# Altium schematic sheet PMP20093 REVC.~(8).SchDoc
size 431 x 279 mm; Date: Not shown in title block; ApprovedBy: Not shown in title block; CheckedBy: Not shown in title block; Author: Not shown in title block; CompanyName: Not shown in title block; Engineer: Not shown in title block; Organization: Not shown in title block; Address1: Not shown in title block; Address2: Not shown in title block; Address3: Not shown in title block; Address4: Not shown in title block; DocumentNumber: 1; Revision: Use project parameter SCH_Rev; SheetNumber: 1; SheetTotal: 1; PageSetup: Record=PageOptions¦CenterHorizontal=True¦CenterVertical=True¦PrintScale=1.00¦XCorrection=1.00¦YCorrection=1.00¦PrintKind=0¦BorderSize=5000000¦LeftOffset=0¦BottomOffset=0¦Orientation=2¦PaperLength=1000¦PaperWidth=1000¦Scale=100¦PaperSource=15¦PrintQuality=600¦MediaType=1¦DitherType=10¦PaperKind=Letter¦PrintScaleMode=1
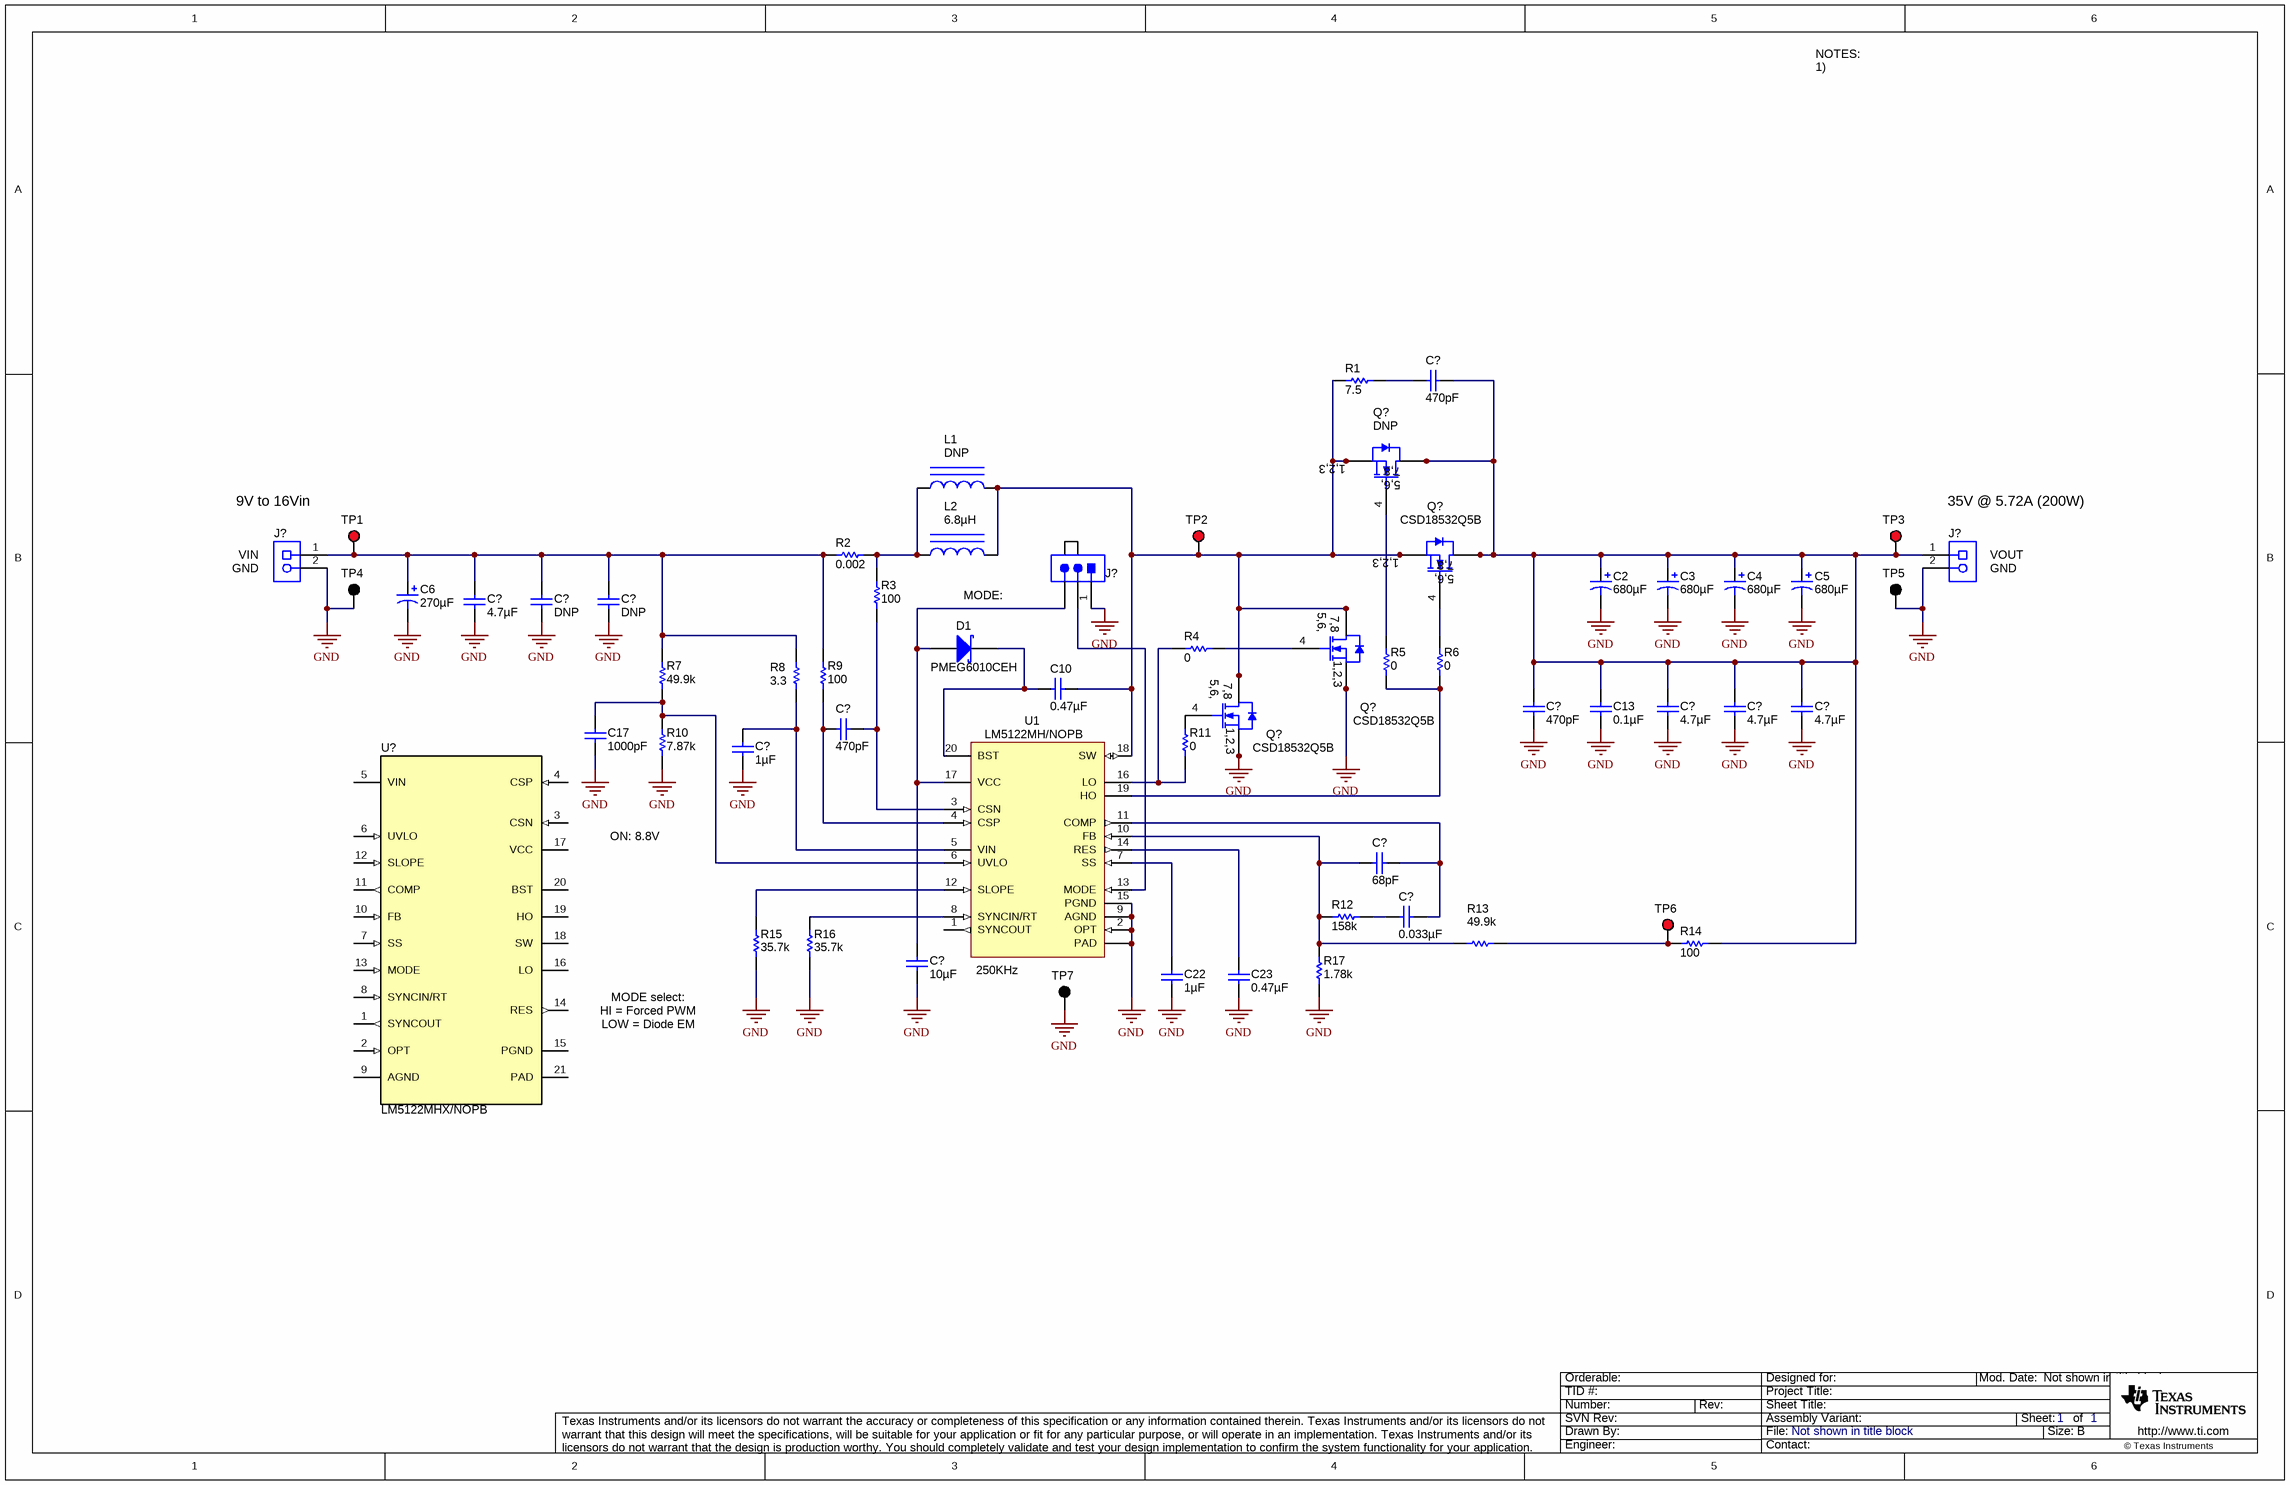
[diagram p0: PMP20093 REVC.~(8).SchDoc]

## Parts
(Parts that share a designator on the sheet are numbered #1, #2 ... from top to bottom, then left to right.)
C2  ValueDisplayed: 680µF  [ZL_1250x2500]  (hidden comment: 50ZL680MEFC12.5X25)
C3  ValueDisplayed: 680µF  [ZL_1250x2500]  (hidden comment: 50ZL680MEFC12.5X25)
C4  ValueDisplayed: 680µF  [ZL_1250x2500]  (hidden comment: 50ZL680MEFC12.5X25)
C5  ValueDisplayed: 680µF  [ZL_1250x2500]  (hidden comment: 50ZL680MEFC12.5X25)
C6  ValueDisplayed: 270µF  [SM_RADIAL_10BMM]  (hidden comment: EEHZA1V271P)
C10  ValueDisplayed: 0.47µF  [0603]  (hidden comment: GRM188R71E474KA12D)
C13  ValueDisplayed: 0.1µF  [0603]  (hidden comment: C1608X7R1H104K080AA)
C17  ValueDisplayed: 1000pF  [0603]  (hidden comment: GRM188R71H102KA01D)
C22  ValueDisplayed: 1µF  [0603]  (hidden comment: C1608X7R1E105K080AB)
C23  ValueDisplayed: 0.47µF  [0603]  (hidden comment: GRM188R71E474KA12D)
C?#1  ValueDisplayed: 470pF  [0603]  (hidden comment: C1608C0G2A471J)
C?#2  ValueDisplayed: 4.7µF  [1210_270]  (hidden comment: GRM32ER71H475KA88L)
C?#3  ValueDisplayed: DNP  [1210_270]
C?#4  ValueDisplayed: DNP  [1210_270]
C?#5  ValueDisplayed: 470pF  [0603]  (hidden comment: C1608C0G2A471J)
C?#6  ValueDisplayed: 4.7µF  [1210_270]  (hidden comment: GRM32ER71H475KA88L)
C?#7  ValueDisplayed: 4.7µF  [1210_270]  (hidden comment: GRM32ER71H475KA88L)
C?#8  ValueDisplayed: 4.7µF  [1210_270]  (hidden comment: GRM32ER71H475KA88L)
C?#9  ValueDisplayed: 470pF  [0603]  (hidden comment: C1608C0G2A471J)
C?#10  ValueDisplayed: 1µF  [0805_HV]  (hidden comment: C2012X7R1H105K125AB)
C?#11  ValueDisplayed: 68pF  [0603]  (hidden comment: GRM1885C1H680JA01D)
C?#12  ValueDisplayed: 0.033µF  [0603]  (hidden comment: GRM188R71H333KA61D)
C?#13  ValueDisplayed: 10µF  [0805_HV]  (hidden comment: GRM21BZ71E106KE15L)
D1  PMEG6010CEH  [SOD-123F]
J?#1  ED120/2DS  [On-Shore_ED120_2DS]  (value not drawn)
J?#2  ED120/2DS  [On-Shore_ED120_2DS]  (value not drawn)
J?#3  PEC03SAAN  [CONN_PEC03SAAN]  (value not drawn)
L1  ValueDisplayed: DNP  [XAL1010]
L2  ValueDisplayed: 6.8µH  [IHLP8787MZ]  (hidden comment: IHLP8787MZER6R8M5A)
Q?#1  value DNP  [DNK0008A]
Q?#2  CSD18532Q5B  [DNK0008A]
Q?#3  CSD18532Q5B  [DNK0008A]
Q?#4  CSD18532Q5B  [DNK0008A]
R1  value 7.5  [2010M]  (hidden comment: CRM2010-JW-7R5ELF)
R2  value 0.002  [2512]  (hidden comment: CSNL2512FT2L00)
R3  ValueDisplayed: 100  [0603]  (hidden comment: CRCW0603100RFKEA)
R4  ValueDisplayed: 0  [0603]  (hidden comment: CRCW06030000Z0EA)
R5  ValueDisplayed: 0  [0603]  (hidden comment: CRCW06030000Z0EA)
R6  ValueDisplayed: 0  [0603]  (hidden comment: CRCW06030000Z0EA)
R7  value 49.9k  [0603]  (hidden comment: CRCW060349K9FKEA)
R8  value 3.3  [0603_HV]  (hidden comment: CRCW06033R30JNEA)
R9  ValueDisplayed: 100  [0603]  (hidden comment: CRCW0603100RFKEA)
R10  ValueDisplayed: 7.87k  [0603]  (hidden comment: CRCW06037K87FKEA)
R11  ValueDisplayed: 0  [0603]  (hidden comment: CRCW06030000Z0EA)
R12  ValueDisplayed: 158k  [0603]  (hidden comment: CRCW0603158KFKEA)
R13  value 49.9k  [0603]  (hidden comment: CRCW060349K9FKEA)
R14  value 100  [0603]  (hidden comment: CRCW0603100RFKEA)
R15  ValueDisplayed: 35.7k  [0603]  (hidden comment: CRCW060335K7FKEA)
R16  ValueDisplayed: 35.7k  [0603]  (hidden comment: CRCW060335K7FKEA)
R17  ValueDisplayed: 1.78k  [0603]  (hidden comment: CRCW06031K78FKEA)
TP1  5010  [Keystone5010]  (value not drawn)
TP2  5010  [Keystone5010]  (value not drawn)
TP3  5010  [Keystone5010]  (value not drawn)
TP4  5011  [Keystone5011]  (value not drawn)
TP5  5011  [Keystone5011]  (value not drawn)
TP6  5010  [Keystone5010]  (value not drawn)
TP7  5011  [Keystone5011]  (value not drawn)
U1  LM5122MH/NOPB  [PWP0020A_N]
U?  LM5122MHX/NOPB  [PWP0020A_N]

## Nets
GND: C2.2(-) C3.2(-) C4.2(-) C5.2(-) C6.2(-) C13.1 C17.2 C22.2 C23.1 C?#2.2 C?#3.2 C?#4.2 C?#5.2 C?#6.2 C?#7.2 C?#8.2 C?#10.1 C?#13.2 J?#1.2 J?#2.2 J?#3.1 Q?#3.1(S) Q?#3.2(S) Q?#3.3(S) Q?#4.1(S) Q?#4.2(S) Q?#4.3(S) R10.1 R15.1 R16.1 R17.1 TP4.1 TP5.1 TP7.1 U1.2(OPT) U1.9(AGND) U1.15(PGND) U1.21(PAD)
NetC2_1: C2.1(+) C3.1(+) C4.1(+) C5.1(+) C13.2 C?#1.1 C?#5.1 C?#6.1 C?#7.1 C?#8.1 J?#2.1 Q?#1.5(D) Q?#1.6(D) Q?#1.7(D) Q?#1.8(D) Q?#1.9(D) Q?#2.5(D) Q?#2.6(D) Q?#2.7(D) Q?#2.8(D) Q?#2.9(D) R14.2 TP3.1
NetC6_1: C6.1(+) C?#2.1 C?#3.1 C?#4.1 J?#1.1 R2.1 R7.2 R8.1 R9.2 TP1.1
NetC10_1: C10.1 D1.1(K) U1.20(BST)
NetC10_2: C10.2 L1.2 L2.2 Q?#1.1(S) Q?#1.2(S) Q?#1.3(S) Q?#2.1(S) Q?#2.2(S) Q?#2.3(S) Q?#3.5(D) Q?#3.6(D) Q?#3.7(D) Q?#3.8(D) Q?#3.9(D) Q?#4.5(D) Q?#4.6(D) Q?#4.7(D) Q?#4.8(D) Q?#4.9(D) R1.1 TP2.1 U1.18(SW)
NetC17_1: C17.1 R7.1 R10.2 U1.6(UVLO)
NetC22_1: C22.1 U1.7(SS)
NetC23_2: C23.2 U1.14(RES)
NetC?#1_2: C?#1.2 R1.2
NetC?#9_1: C?#9.1 R3.1 U1.3(CSN)
NetC?#9_2: C?#9.2 R9.1 U1.4(CSP)
NetC?#10_2: C?#10.2 R8.2 U1.5(VIN)
NetC?#11_1: C?#11.1 C?#12.1 U1.11(COMP)
NetC?#11_2: C?#11.2 R12.1 R13.1 R17.2 U1.10(FB)
NetC?#12_2: C?#12.2 R12.2
NetC?#13_1: C?#13.1 D1.2(A) J?#3.3 U1.17(VCC)
NetJ?#3_2: J?#3.2 U1.13(MODE)
NetL1_1: L1.1 L2.1 R2.2 R3.2
NetQ?#1_4: Q?#1.4(G) R5.2
NetQ?#2_4: Q?#2.4(G) R6.2
NetQ?#3_4: Q?#3.4(G) R4.1
NetQ?#4_4: Q?#4.4(G) R11.2
NetR4_2: R4.2 R11.1 U1.16(LO)
NetR5_1: R5.1 R6.1 U1.19(HO)
NetR13_2: R13.2 R14.1 TP6.1
NetR15_2: R15.2 U1.12(SLOPE)
NetR16_2: R16.2 U1.8(SYNCIN/RT)

Not connected (* = marked no-connect by the designer): U1 1(SYNCOUT); U? 1(SYNCOUT) 2(OPT) 3(CSN) 4(CSP) 5(VIN) 6(UVLO) 7(SS) 8(SYNCIN/RT) 9(AGND) 10(FB) 11(COMP) 12(SLOPE) 13(MODE) 14(RES) 15(PGND) 16(LO) 17(VCC) 18(SW) 19(HO) 20(BST) 21(PAD)

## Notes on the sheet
- NOTES:
  1)
- 9V to 16Vin
- 35V @ 5.72A (200W)
- (near J?#1) VIN
- (near J?#1) GND
- (near J?#2) VOUT
- (near J?#2) GND
- MODE:
- ON: 8.8V
- (near U1) 250KHz
- MODE select:
- HI = Forced PWM
- LOW = Diode EM

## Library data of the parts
C2-C5 = 50ZL560MEFC12.5X25: CAP, AL, 680 µF, 50 V, +/- 20%, 2.86A, 0.021 ohm, TH; Manufacturer: Rubycon; Polarized: Y; CompType: Capacitor; Value: 680uF; U/M: EA; Cap_F: 0.00056; Tolerance_%: 20; VDC_V: 50; Value2: 50V; ESR_ohm: 0.023; IRMS_A: 2.41; TaMin_C: -40; TaMax_C: 105; Cap_Case: 12.5x25mm; AEC Category: Q200; AEC Qualified: N
C6 = EEHZA1V271P: CAP, Polymer Hybrid, 270 µF, 35 V, +/- 20%, 20 ohm, 10x10 SMD; Manufacturer: Panasonic; Polarized: Y; CompType: Capacitor; Value: 270uF; U/M: EA; Cap_F: 0.00027; Tolerance_%: 20; Value1: 20 ohm; VDC_V: 35; Value2: 35V; IRMS_A: 2.5; TaMin_C: -55; TaMax_C: 105; AEC Category: Q200
C10 C23 = GRM188R71E474KA12D: CAP, CERM, 0.47uF, 25V, +/-10%, X7R, 0603; Manufacturer: MuRata; Polarized: N; CompType: Capacitor; U/M: EA; Cap_F: 0.00000047; Tolerance_%: 10; Value1: Unknown; VDC_V: 25; TaMin_C: -55; TaMax_C: 125
C13 = C1608X7R1H104K080AA: CAP, CERM, 0.1 µF, 50 V, +/- 10%, X7R, 0603; Manufacturer: TDK; Polarized: N; CompType: Capacitor; Value: 0.1uF; U/M: EA; Cap_F: 0.0000001; Tolerance_%: 10; ESR_ohm: 0.0296; Value1: 0.0296 ohm; VDC_V: 50; Value2: 50V; IRMS_A: 0.97199; TaMin_C: -55; TaMax_C: 125; AEC Category: Q200; SizeArea_mm2: 1.28; SizeAreaWB_mm2: 4.68; SizeX_mm: 1.6; SizeY_mm: 0.8; SizeZ_mm: 1
C17 = GRM188R71H102KA01D: CAP, CERM, 1000pF, 50V, +/-10%, X7R, 0603; Manufacturer: MuRata; Polarized: N; CompType: Capacitor; U/M: EA; Cap_F: 0.000000001; Tolerance_%: 10; Value1: Unknown; VDC_V: 50; TaMin_C: -55; TaMax_C: 125
C22 = C1608X7R1E105K080AB: CAP, CERM, 1 µF, 25 V, +/- 10%, X7R, 0603; Manufacturer: TDK; Polarized: N; CompType: Capacitor; Value: 1uF; U/M: EA; Cap_F: 0.000001; Tolerance_%: 10; Value1: Unknown; VDC_V: 25; Value2: 25V; TaMin_C: -55; TaMax_C: 125; AEC Category: Q200
C?#1 C?#5 C?#9 = C1608C0G2A471J: CAP, CERM, 470 pF, 100 V, +/- 5%, C0G/NP0, 0603; Manufacturer: TDK; Polarized: N; CompType: Capacitor; Value: 470pF; U/M: EA; Cap_F: 0.00000000047; Tolerance_%: 5; ESR_ohm: 0.0714; Value1: 0.0714 ohm; VDC_V: 100; Value2: 100V; TaMin_C: -55; TaMax_C: 125; SizeArea_mm2: 1.28; SizeAreaWB_mm2: 4.68; SizeX_mm: 1.6; SizeY_mm: 0.8; SizeZ_mm: 1; AEC Category: Q200
C?#2 C?#6-C?#8 = GRM32ER71H475KA88L: CAP, CERM, 4.7 µF, 50 V, +/- 10%, X7R, 1210; Manufacturer: MuRata; Polarized: N; CompType: Capacitor; Value: 4.7uF; U/M: EA; Cap_F: 0.0000047; Tolerance_%: 10; ESR_ohm: 0.002; Value1: 0.002 ohm; VDC_V: 50; Value2: 50V; TaMin_C: -55; TaMax_C: 125; Cap_Case: 1210; SizeArea_mm2: 8; SizeAreaWB_mm2: 14.7; SizeX_mm: 3.2; SizeY_mm: 2.5; SizeZ_mm: 2.7; AEC Category: Q200
C?#3 C?#4 = GRM32ER71H475KA88L: CAP, CERM, 1210; Polarized: N; CompType: Capacitor; U/M: EA; Tolerance_%: 10; ESR_ohm: 0.002; TaMin_C: -55; TaMax_C: 125; Cap_Case: 1210; SizeArea_mm2: 8; SizeAreaWB_mm2: 14.7; AEC Category: Q200
C?#10 = C2012X7R1H105K125AB: CAP, CERM, 1 µF, 50 V, +/- 10%, X7R, 0805; Manufacturer: TDK; Polarized: N; CompType: Capacitor; Value: 1uF; U/M: EA; Cap_F: 0.000001; Tolerance_%: 10; ESR_ohm: 0.008782; Value1: 0.008782 ohm; VDC_V: 50; Value2: 50V; IRMS_A: 2.20488; TaMin_C: -55; TaMax_C: 125; Cap_Case: 0805; SizeArea_mm2: 2.5; SizeAreaWB_mm2: 6.75; SizeX_mm: 2; SizeY_mm: 1.25; SizeZ_mm: 1.45; AEC Category: Q200
C?#11 = GRM1885C1H680JA01D: CAP, CERM, 68 pF, 50 V, +/- 5%, C0G/NP0, 0603; Manufacturer: MuRata; Polarized: N; CompType: Capacitor; Value: 68pF; U/M: EA; Cap_F: 0.000000000068; Tolerance_%: 5; Value1: Unknown; VDC_V: 50; Value2: 50V; TaMin_C: -55; TaMax_C: 125; SizeArea_mm2: 1.28; SizeAreaWB_mm2: 4.68; SizeX_mm: 1.6; SizeY_mm: 0.8; SizeZ_mm: 1; AEC Category: Q200
C?#12 = GRM188R71H333KA61D: CAP, CERM, 0.033 µF, 50 V, +/- 10%, X7R, 0603; Manufacturer: MuRata; Polarized: N; CompType: Capacitor; Value: 0.033uF; U/M: EA; Cap_F: 0.000000033; Tolerance_%: 10; Value1: Unknown; VDC_V: 50; Value2: 50V; TaMin_C: -55; TaMax_C: 125; SizeArea_mm2: 1.28; SizeAreaWB_mm2: 4.68; SizeX_mm: 1.6; SizeY_mm: 0.8; SizeZ_mm: 1; AEC Category: Q200
C?#13 = GRM21BZ71E106KE15L: CAP, CERM, 10 µF, 25 V, +/- 10%, X7R, 0805; Manufacturer: MuRata; Polarized: N; CompType: Capacitor; Value: 10uF; U/M: EA; Cap_F: 0.00001; Tolerance_%: 10; Value1: Unknown; VDC_V: 25; Value2: 25V; TaMin_C: -55; TaMax_C: 125; Cap_Case: 0805; SizeArea_mm2: 2.5; SizeAreaWB_mm2: 6.75; SizeX_mm: 2; SizeY_mm: 1.25; SizeZ_mm: 1.45; AEC Category: Q200
D1 = PMEG6010CEH,115: Diode, Schottky, 60V, 1A, SOD-123F; Manufacturer: NXP Semiconductor; U/M: EA; Vf_V: 0.57; Value2: 0.57V; Io_A: 1; Vr_V: 60; TJmax_C: 150
J?#1 J?#2 = ED120/2DS: Terminal Block, 5.08 mm, 2x1, Brass, TH; Manufacturer: On-Shore Technology; SymbolCreator: a0412235; Pitch_mm: 5.08; Gender: Female; Shrouded: N; Row_Count: 1; Current_A: 15; Voltage_V: 300; Cert_CULUS: Y
J?#3 = PEC03SAAN: Header, 100mil, 3x1, Tin, TH; Manufacturer: Sullins Connector Solutions; SymbolCreator: a0799628; Pitch_mm: 2.54; Gender: Male; Shrouded: N; Row_Count: 1; Current_A: 3; Voltage_V: 1800; Cert_UL: Y
L1 = XAL1010-222MEB: Inductor, SMD, alternate footprint; U/M: EA
L2 = IHLP8787MZER100M5A: Inductor, Shielded, 6.8 µH, 36A, 0.00284 ohm, AEC-Q200 Grade 0, SMD; Manufacturer: Vishay-Dale; Value: 6.8uH; AEC Category: Q200; AEC Qualified: Y; AEC Grade: 0
Q?#1 = CSD18532Q5B: MOSFET, N-CH, DNP; Alternate Manufacturer: None; U/M: EA; ChType: N; IdsMax_A: 172; SizeAreaWB_mm2: 56; SizeArea_mm2: 30; AEC Category: Q101
Q?#2-Q?#4 = CSD18532Q5B: MOSFET, N-CH, 60 V, 172 A, DNK0008A (VSON-CLIP-8); Manufacturer: Texas Instruments; Alternate Manufacturer: None; U/M: EA; ChType: N; Value: 60V; VdsMax_V: 60; Value1: 3.3 ohm; Rdson45_ohm: 3.3; Value2: 27 nC; QgTyp_nC: 27; Vgs_V: 1.6; IdsMax_A: 172; SizeAreaWB_mm2: 56; SizeArea_mm2: 30; SizeX_mm: 6; SizeY_mm: 5; SizeZ_mm: 1; AEC Category: Q101
R1 = CRM2010-JW-7R5ELF: RES, 7.5 ohm, 5%, 1W, 2010; Manufacturer: Bourns; CompType: Resistor; Value_Code: 7R50; Tolerance_%: 5; Power_W: 1; VDC_V: 3; TempCo: 100 ppm/C; EIA_Code: E24; U/M: EA
R2 = CSNL2512FT2L00: RES, 0.002 ohm, 1%, 2W, 2512; Manufacturer: Stackpole Electronics Inc; CompType: Resistor; Value_Code: R002; Tolerance_%: 1; Power_W: 2; VDC_V: 200; TempCo: 50 ppm/C; U/M: EA
R3 R9 = CRCW0603100RFKEA: RES, 100, 1%, 0.1 W, 0603; Manufacturer: Vishay-Dale; CompType: Resistor; Value: 100; Value_Code: 100R; Tolerance_%: 1; Power_W: 0.1; Value2: 0.1W; VDC_V: 75; TempCo: 100 ppm/C; EIA_Code: E96; U/M: EA; SizeArea_mm2: 1.28; SizeX_mm: 1.6; SizeY_mm: 0.8; AEC Category: Q200
R4-R6 R11 = CRCW06030000Z0EA: RES, 0, 5%, 0.1 W, 0603; Manufacturer: Vishay-Dale; CompType: Resistor; Value: 0; Value_Code: 0000; Tolerance_%: 5; Power_W: 0.1; Value2: 0.1W; VDC_V: 75; TempCo: 200 ppm/C; EIA_Code: E24; U/M: EA; SizeArea_mm2: 1.28; SizeX_mm: 1.6; SizeY_mm: 0.8; SizeZ_mm: 1; AEC Category: Q200
R7 R13 = CRCW060349K9FKEA: RES, 49.9k ohm, 1%, 0.1W, 0603; Manufacturer: Vishay-Dale; CompType: Resistor; Res_ohm: 49900; Value_Code: 49k9; Tolerance_%: 1; Power_W: 0.1; VDC_V: 75; TempCo: 100 ppm/C; EIA_Code: E96; U/M: EA
R8 = CRCW06033R30JNEA: RES, 3.3 ohm, 5%, 0.1W, 0603; Manufacturer: Vishay-Dale; CompType: Resistor; Value_Code: 3R30; Tolerance_%: 5; Power_W: 0.1; VDC_V: 75; TempCo: 200 ppm/C; EIA_Code: E24; U/M: EA
R10 = CRCW06037K87FKEA: RES, 7.87 k, 1%, 0.1 W, 0603; Manufacturer: Vishay-Dale; CompType: Resistor; Value: 7.87k; Res_ohm: 7870; Value_Code: 7k87; Tolerance_%: 1; Power_W: 0.1; Value2: 0.1W; VDC_V: 75; TempCo: 100 ppm/C; EIA_Code: E96; U/M: EA; AEC Category: Q200
R12 = CRCW0603158KFKEA: RES, 158 k, 1%, 0.1 W, 0603; Manufacturer: Vishay-Dale; CompType: Resistor; Value: 158k; Res_ohm: 158000; Tolerance_%: 1; Power_W: 0.1; Value2: 0.1W; VDC_V: 75; TempCo: 100 ppm/C; EIA_Code: E96; U/M: EA; AEC Category: Q200
R14 = CRCW0603100RFKEA: RES, 100 ohm, 1%, 0.1W, 0603; Manufacturer: Vishay-Dale; CompType: Resistor; Value_Code: 100R; Tolerance_%: 1; Power_W: 0.1; VDC_V: 75; TempCo: 100 ppm/C; EIA_Code: E96; U/M: EA
R15 R16 = CRCW060335K7FKEA: RES, 35.7 k, 1%, 0.1 W, 0603; Manufacturer: Vishay-Dale; CompType: Resistor; Value: 35.7k; Res_ohm: 35700; Value_Code: 35k7; Tolerance_%: 1; Power_W: 0.1; Value2: 0.1W; VDC_V: 75; TempCo: 100 ppm/C; EIA_Code: E96; U/M: EA; AEC Category: Q200
R17 = CRCW06031K78FKEA: RES, 1.78 k, 1%, 0.1 W, 0603; Manufacturer: Vishay-Dale; CompType: Resistor; Value: 1.78k; Res_ohm: 1780; Value_Code: 1k78; Tolerance_%: 1; Power_W: 0.1; Value2: 0.1W; VDC_V: 75; TempCo: 100 ppm/C; EIA_Code: E96; U/M: EA; AEC Category: Q200
TP1-TP3 TP6 = 5010: Test Point, Multipurpose, Red, TH; Manufacturer: Keystone; CompType: Test Point Loop; U/M: EA
TP4 TP5 TP7 = 5011: Test Point, Multipurpose, Black, TH; Manufacturer: Keystone; CompType: Test Point Loop; U/M: EA
U1 = LM5122MH/NOPB: Wide Input Synchronous Boost Controller with Multiple Phase Capability, PWP0020A; Alternate Manufacturer: None; Manufacturer: Texas Instruments; SymbolCreator: a0411947; CompType: IC; U/M: EA
U? = LM5122MHX/NOPB: Wide Input Synchronous Boost Controller with Multiple Phase Capability, PWP0020A (TSSOP-20); Alternate PartNumber: LM5122MHE/NOPB; Manufacturer: Texas Instruments; SymbolCreator: a0411947; SizeArea_mm2: 41.6; SizeAreaWB_mm2: 71.4; SizeX_mm: 6.4; SizeY_mm: 6.5; SizeZ_mm: 1.2; CompType: IC; U/M: EA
